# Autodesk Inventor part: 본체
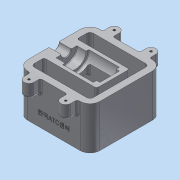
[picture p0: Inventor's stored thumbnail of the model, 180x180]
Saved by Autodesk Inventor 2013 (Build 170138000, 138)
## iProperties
Created: 2018-01
Part Number: 본체
Material: 알루미늄 6061
Document SubType Name: Modeling
Designer: dgall
Density: 2.71 g/cm^3
Mass: 998.422 g
Surface Area: 835.869 cm^2
Volume: 368.421 cm^3
Author: dgall
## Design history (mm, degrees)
sketch "스케치1"
  geometry: L1 (-55, 55)-(55, 55); L2 (55, 55)-(55, -55); L3 (55, -55)-(-55, -55); L4 (-55, -55)-(-55, 55); 3 further points
  constraints: 8 end point, 2 midpoint, 2 parallel, 2 perpendicular, 1 horizontal, 1 horizontal alignment, 1 vertical alignment
  dimensions: "d0" = 110 distance of L1.start L1.end
extrude "돌출1" new body sketch "스케치1" distance "d2" = 65; taper "d3" = 0 deg
sketch "스케치2"
  geometry: L1 (-55, 55)-(-55, -55) reference; L2 (-55, -55)-(55, -55) reference; L3 (55, -55)-(55, 55) reference; L4 (20.5, -55)-(20.5, -65); L5 (35.5, -55)-(35.5, -65); A1 r 7.5 centre (28, -65) between (20.5, -65) and (35.5, -65); 1 further point
  constraints: 4 end point, 2 parallel, 2 point on circle, 2 point on line, 2 tangent, 1 centre point
  dimensions: "d4" = 83 distance from line of A1.centre L1; "d5" = 10 distance from line of L2 A1.centre; "d6" = 7.5 radius of A1
extrude "돌출2" join sketch "스케치2" distance "d7" = 20; taper "d8" = 0 deg
node "작업 평면1"
node "작업 평면2"
sketch "스케치3"
  geometry: L1 (55, -55)-(55, 55) reference; L2 (-45, 45)-(45, 45); L3 (45, 45)-(45, -45); L4 (45, -45)-(-45, -45); L5 (-45, -45)-(-45, 45); 3 further points
  constraints: 8 end point, 2 midpoint, 2 parallel, 2 perpendicular, 1 horizontal, 1 horizontal alignment, 1 vertical alignment
  dimensions: "d9" = 10 distance between parallel lines of L1 L3
extrude "돌출3" cut sketch "스케치3" stored distance "d10" = 20; taper "d11" = 0 deg
hole "구멍1" diameter "d14" = 3.459; stored, may be unused: countersink angle "d18" = 90 deg, drill point angle "d20" = 118 deg; dims "d12" = 10, "d13" = 10, "d15" = 9, "d16" = 4, "d17" = 2, "d19" = 11
sketch "스케치4"
  geometry: L1 (-45, -45)-(-45, 45) reference; L2 (-55, 55)-(-55, -55) reference; L3 (55, -55)-(55, 55) reference; L4 (-45, 25)-(35, 25); L5 (35, 25)-(35, -25); L6 (35, -25)-(-45, -25); 2 further points
  constraints: 6 end point, 3 perpendicular, 2 point on line, 1 horizontal alignment, 1 midpoint
  dimensions: "d21" = 20 distance between parallel lines of L3 L5; "d22" = 50 distance from line of L6.end L4
extrude "돌출4" join sketch "스케치4" distance "d23" = 65; taper "d24" = 0 deg
sketch "스케치5"
  geometry: L1 (-55, 55)-(-55, -55) reference; L2 (55, -55)-(55, 55) reference; L3 (-55, 7.5)-(-36, 7.5); L4 (-36, 7.5)-(-36, 16); L5 (-36, 16)-(-22, 16); L6 (-22, 16)-(-22, 20); L7 (-22, 20)-(25, 20); L8 (25, 20)-(25, 15); L9 (25, 15)-(30, 15); L10 (30, 15)-(30, 0); L11 (30, 0)-(-55, 0); L12 (-55, 0)-(-55, 7.5); 1 further point
  constraints: 20 end point, 6 parallel, 3 perpendicular, 1 midpoint, 1 point on line
  dimensions: "d25" = 15 diameter of L3 L11; "d27" = 32 diameter of L5 L11; "d28" = 40 diameter of L7 L11; "d29" = 30 diameter of L9 L11; "d30" = 14 distance of L4.end L5.end; "d31" = 47 distance of L6.end L7.end; "d32" = 5 distance of L8.end L9.end; "d33" = 19 distance of L3.start L3.end
revolve "회전1" sketch "스케치5" stored, may be unused: angle "d34" = 90 deg
sketch "스케치6"
  geometry: L1 (-22, 49)-(-22, 65) reference; L2 (-22, 45)-(-22, 65) reference; L3 (25, 50)-(25, 65) reference; L4 (25, 45)-(25, 65) reference; L5 (-55, 0)-(-55, 65) reference; L6 (-22, 45)-(25, 45) reference; L7 (-22, 65)-(25, 65) reference; L8 (35, 65)-(35, 0) reference; L9 (-45, 0)-(35, 0) reference; L10 (45, 0)-(-45, 0) reference; L11 (45, 65)-(45, 0) reference; L12 (-45, 65)-(45, 65) reference; L13 (-45, 65)-(-45, 0) reference; L14 (35, 30)-(-45, 8.564); L15 (-45, 8.564)-(-45, 0); L16 (-17, 45)-(-17, 39.243); L17 (-17, 39.243)-(-55, 29.061); L18 (20, 45)-(20, 31.157); L19 (20, 31.157)-(-55, 11.061); L20 (35, 0)-(-45, 0); 3 further points
  constraints: 14 end point, 7 point on line, 2 midpoint, 2 parallel, 1 perpendicular, 1 vertical alignment
  dimensions: "d43" = 105 deg angle of L15 L14; "d44" = 30 distance from line of L9 L14.start; "d45" = 18.5 distance of L16.start point (1.5, 45); "d46" = 18.5 distance of L18.start point (1.5, 45); "d47" = 75 deg angle of L17 L5; "d49" = 18 distance of L19.end L17.end; "d51" = 5 distance between parallel lines of L19 L14
  node "투영된 루프1"
extrude "돌출5" cut sketch "스케치6" stored distance "d52" = 30; taper "d53" = 0 deg
extrude "돌출6" cut sketch "스케치6" stored distance "d54" = 50; taper "d55" = 0 deg
sketch "스케치7"
  geometry: L1 (-22, 20)-(25, 20) reference; L2 (25, -20)-(-22, -20) reference; L3 (-17, 15)-(20, 15); L4 (20, 15)-(20, -15); L5 (20, -15)-(-17, -15); L6 (-17, -15)-(-17, 15); 6 further points
  constraints: 8 end point, 5 midpoint, 2 parallel, 2 vertical alignment, 1 horizontal, 1 horizontal alignment, 1 perpendicular
  dimensions: "d59" = 30 distance between parallel lines of L5 L3; "d61" = 37 distance of L3.start L3.end
extrude "돌출7" cut sketch "스케치7" stored distance "d62" = 50; taper "d63" = 0 deg
fillet "모깎기1" dims "d64" = 15
fillet "모깎기2" dims "d65" = 5
fillet "모깎기3" dims "d66" = 1
chamfer "모따기1" distance "d67" = 1; stored, may be unused: second distance "d68" = 2, angle "d69" = 45 deg
fillet "모깎기4" dims "d70" = 3
fillet "모깎기5" dims "d71" = 3
fillet "모깎기6" dims "d72" = 3
fillet "모깎기7" dims "d73" = 3
fillet "모깎기8" dims "d74" = 3
fillet "모깎기9" dims "d75" = 3
fillet "모깎기10" dims "d76" = 3
fillet "모깎기11" dims "d77" = 3
node "작업 평면3"
sketch "스케치8"
  geometry: L1 (-55, 65)-(-55, 0) reference; L2 (-17.5, 65)-(17.5, 65) reference; L3 (40, 0)-(-40, 0) reference; 2 further points
  constraints: 1 other
  dimensions: "d79" = 55 distance from line of point (0, 20) L1; "d80" = 20 distance from line of L3 point (0, 20)
feature "엠보싱1" sketch "스케치8" dims "d81" = 0.5, "d82" = 0
fillet "모깎기12" dims "d83" = 3
node "솔리드1"
mirror "대칭1"
mirror "대칭2"
mirror "대칭3"
mirror "대칭4"
other parameters: "d78" = 161.75
